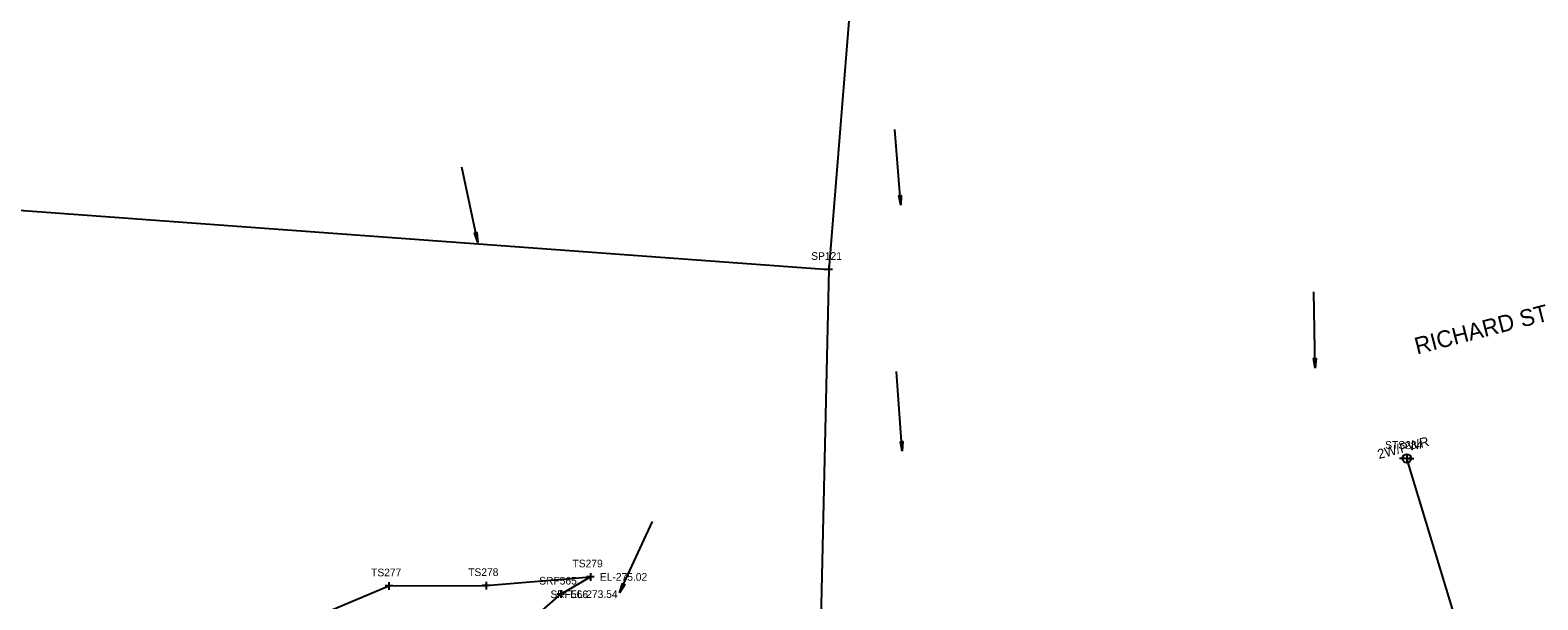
# Model space of a CAD drawing. Extents: x 818717 to 846077, y 440014 to 541392.
# Drawn here: x 831333 to 832121, y 493437 to 493734 of the extents above; entities that cross this region are included whole.
import ezdxf

# ---------------------------------------------------------------- set-up
doc = ezdxf.new("R2010")
doc.units = 0
for name, color, linetype in [('SURVEY - DRAINAGE - Natural Features Text', 7, 'Continuous'), ('SURVEY - DTM - Breaklines', 7, 'Continuous'), ('SURVEY - DTM - Breaklines - Points - Elevations', 7, 'Continuous'), ('SURVEY - DTM - Breaklines - Points - Locators', 7, 'Continuous'), ('SURVEY - DTM - Breaklines - Points - Numbers', 7, 'Continuous'), ('SURVEY - PROPERTY - Owners', 7, 'Continuous'), ('SURVEY - PROPERTY - Property Lines', 7, 'Continuous'), ('SURVEY - PROPERTY - Property Lines - Points - Locators', 7, 'Continuous'), ('SURVEY - PROPERTY - Property Lines - Points - Numbers', 7, 'Continuous'), ('SURVEY - UTILITIES - Electric (Overhead) with Text', 7, 'Continuous'), ('SURVEY - UTILITIES - Poles and Miscellaneous - Points - Locators', 7, 'Continuous'), ('SURVEY - UTILITIES - Poles and Miscellaneous - Points - Numbers', 7, 'Continuous'), ('SURVEY - UTILITIES - Poles and Miscellaneous with Text', 7, 'Continuous')]:
    doc.layers.add(name, color=color, linetype=linetype)

msp = doc.modelspace()

# ---------------------------------------------------------------- linework, layer by layer
at = {"layer": 'SURVEY - DRAINAGE - Natural Features Text'}
for p, q in [((831787.98, 493642.47), (831784.82, 493682.04)), ((831567.08, 493623.13), (831558.81, 493662.4)), ((831787.77, 493645.16), (831787.98, 493642.47)), ((831566.52, 493625.77), (831567.08, 493623.13)), ((832004.26, 493557.49), (832003.6, 493597.35)), ((831788.79, 493514.06), (831785.82, 493555.78)), ((832004.22, 493560.19), (832004.26, 493557.49)), ((831788.6, 493516.76), (831788.79, 493514.06)), ((831641.17, 493440.2), (831658.3, 493477.4)), ((831642.3, 493442.66), (831641.17, 493440.2))]:
    msp.add_line(p, q, dxfattribs=at)
for points in [[(831787.98, 493642.47), (831786.93, 493647.46), (831787.63, 493646.86), (831788.23, 493647.56)], [(831567.08, 493623.13), (831565.4, 493627.94), (831566.17, 493627.44), (831566.67, 493628.21)], [(832004.26, 493557.49), (832003.53, 493562.53), (832004.19, 493561.89), (832004.83, 493562.55)], [(831788.79, 493514.06), (831787.79, 493519.05), (831788.48, 493518.45), (831789.08, 493519.15)], [(831641.17, 493440.2), (831642.69, 493445.06), (831643.01, 493444.2), (831643.87, 493444.52)]]:
    msp.add_lwpolyline(points, close=True, dxfattribs=at)
for points in [[(831787.98, 493642.47), (831786.93, 493647.46), (831787.63, 493646.86), (831788.23, 493647.56), (831787.98, 493642.47)], [(831567.08, 493623.13), (831565.4, 493627.94), (831566.17, 493627.44), (831566.67, 493628.21), (831567.08, 493623.13)], [(832004.26, 493557.49), (832003.53, 493562.53), (832004.19, 493561.89), (832004.83, 493562.55), (832004.26, 493557.49)], [(831788.79, 493514.06), (831787.79, 493519.05), (831788.48, 493518.45), (831789.08, 493519.15), (831788.79, 493514.06)], [(831641.17, 493440.2), (831642.69, 493445.06), (831643.01, 493444.2), (831643.87, 493444.52), (831641.17, 493440.2)]]:
    msp.add_lwpolyline(points, dxfattribs=at)
at = {"layer": 'SURVEY - DTM - Breaklines'}
for points in [[(831136.62, 493367.18), (831184.28, 493377.18), (831220.92, 493411.64), (831256.58, 493444.04), (831314.6, 493421.59), (831366.62, 493422.03), (831418.68, 493418.44), (831473.18, 493423.8), (831520.74, 493443.82), (831571.47, 493443.97), (831625.9, 493448.49)], [(831494.72, 493386.71), (831525.33, 493388.55), (831556.41, 493389.9), (831582.94, 493415.51), (831610.44, 493439.5), (831625.9, 493448.49)]]:
    msp.add_lwpolyline(points, dxfattribs=at)
at = {"layer": 'SURVEY - DTM - Breaklines - Points - Locators'}
for p, q in [((831520.74, 493445.82), (831520.74, 493441.82)), ((831571.47, 493445.97), (831571.47, 493441.97)), ((831627.9, 493448.49), (831623.9, 493448.49)), ((831625.9, 493450.49), (831625.9, 493446.49)), ((831522.74, 493443.82), (831518.74, 493443.82)), ((831573.47, 493443.97), (831569.47, 493443.97)), ((831612.44, 493439.5), (831608.44, 493439.5)), ((831610.44, 493441.5), (831610.44, 493437.5))]:
    msp.add_line(p, q, dxfattribs=at)
at = {"layer": 'SURVEY - PROPERTY - Property Lines'}
for p, q in [((831807.71, 494315.11), (831750.35, 493609)), ((830086.25, 493730.81), (831750.35, 493609)), ((831750.35, 493609), (831739.78, 493146.11))]:
    msp.add_line(p, q, dxfattribs=at)
at = {"layer": 'SURVEY - PROPERTY - Property Lines - Points - Locators'}
for p, q in [((831750.35, 493611), (831750.35, 493607)), ((831752.35, 493609), (831748.35, 493609))]:
    msp.add_line(p, q, dxfattribs=at)
at = {"layer": 'SURVEY - UTILITIES - Electric (Overhead) with Text'}
msp.add_line((832147.85, 493195.27), (832052.13, 493510.37), dxfattribs=at)
at = {"layer": 'SURVEY - UTILITIES - Poles and Miscellaneous - Points - Locators'}
for p, q in [((832054.13, 493510.37), (832050.13, 493510.37)), ((832052.13, 493512.37), (832052.13, 493508.37))]:
    msp.add_line(p, q, dxfattribs=at)
at = {"layer": 'SURVEY - UTILITIES - Poles and Miscellaneous with Text'}
for q in [(832048.38, 493510.37), (832055.88, 493510.37)]:
    msp.add_line((832052.13, 493510.37), q, dxfattribs=at)
msp.add_circle((832052.13, 493510.37), 2.25, dxfattribs=at)

# ---------------------------------------------------------------- texts
at = {"layer": 'SURVEY - DTM - Breaklines - Points - Elevations'}
for s, p in [('EL-275.02', (831630.9, 493446.49)), ('EL-273.54', (831615.44, 493437.5))]:
    msp.add_text(s, height=4, dxfattribs=at).set_placement(p)
at = {"layer": 'SURVEY - DTM - Breaklines - Points - Numbers'}
for s, p in [('TS278', (831562.14, 493448.97)), ('TS279', (831616.6, 493453.49)), ('TS277', (831511.45, 493448.82)), ('SRF565', (831599.2, 493444.5)), ('SRF566', (831605.06, 493437.42))]:
    msp.add_text(s, height=4, dxfattribs=at).set_placement(p)
at = {"layer": 'SURVEY - PROPERTY - Owners'}
msp.add_text('RICHARD STEPHEN SULLIVAN, RICHARD VANHURST & WIFE', height=8.75, rotation=14.4738, dxfattribs=at).set_placement((832057.52, 493564.56))
at = {"layer": 'SURVEY - PROPERTY - Property Lines - Points - Numbers'}
msp.add_text('SP121', height=4, dxfattribs=at).set_placement((831741.22, 493614))
at = {"layer": 'SURVEY - UTILITIES - Electric (Overhead) with Text'}
msp.add_text('2W/PWR', height=5, rotation=14.68489, dxfattribs=at).set_placement((832037.62, 493510.02))
at = {"layer": 'SURVEY - UTILITIES - Poles and Miscellaneous - Points - Numbers'}
msp.add_text('STS284', height=4, dxfattribs=at).set_placement((832040.89, 493515.37))

doc.saveas('drawing.dxf')
